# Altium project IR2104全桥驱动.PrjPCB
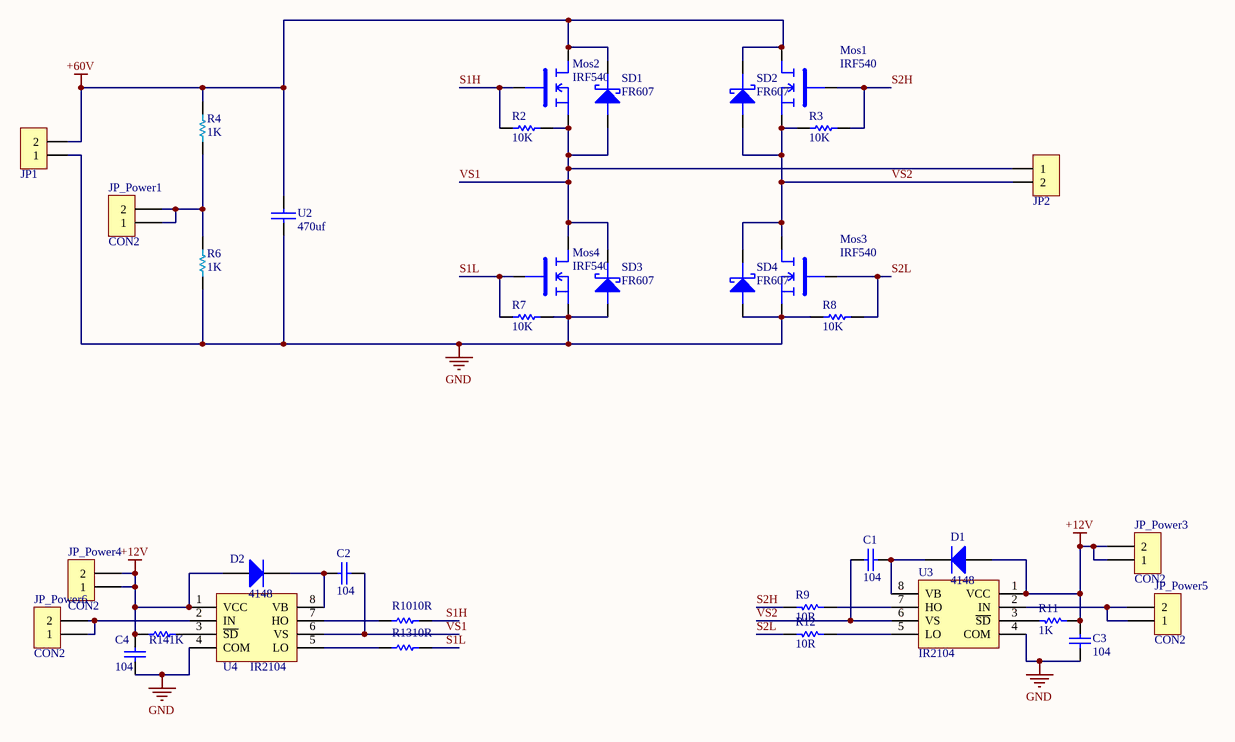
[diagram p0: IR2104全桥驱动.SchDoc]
1 sheet, 36 parts. Net scope: global (net labels, ports and power ports of the same name join across sheets).
Board file: PCB2.PcbDoc

## Sheet IR2104全桥驱动.SchDoc
size A4

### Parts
C1  value 104  [C 0805]  (hidden comment: Cap)
C2  value 104  [C 0805]  (hidden comment: Cap)
C3  value 104  [C 0805]  (hidden comment: Cap)
C4  value 104  [C 0805]  (hidden comment: Cap)
D1  4148  [D1206]
D2  4148  [D1206]
JP1  HDR-1X2  [KF301-2P]  (value not drawn)
JP2  HDR-1X2  [KF301-2P]  (value not drawn)
JP_Power1  CON2  [HDR-1x2]
JP_Power3  CON2  [HDR-1x2]
JP_Power4  CON2  [HDR-1x2]
JP_Power5  CON2  [HDR-1x2]
JP_Power6  CON2  [HDR-1x2]
Mos1  IRF540  [TO220A]
Mos2  IRF540  [TO220A]
Mos3  IRF540  [TO220A]
Mos4  IRF540  [TO220A]
R2  value 10K  [R 0805]  (hidden comment: Res1)
R3  value 10K  [R 0805]  (hidden comment: Res1)
R4  Values: 1K  [R 0805]  (hidden comment: RES)
R6  Values: 1K  [R 0805]  (hidden comment: RES)
R7  value 10K  [R 0805]  (hidden comment: Res1)
R8  value 10K  [R 0805]  (hidden comment: Res1)
R9  value 10R  [R 0805]  (hidden comment: Res1)
R10  value 10R  [R 0805]  (hidden comment: Res1)
R11  value 1K  [R 0805]  (hidden comment: Res1)
R12  value 10R  [R 0805]  (hidden comment: Res1)
R13  value 10R  [R 0805]  (hidden comment: Res1)
R14  value 1K  [R 0805]  (hidden comment: Res1)
SD1  FR607  [R-6]
SD2  FR607  [R-6]
SD3  FR607  [R-6]
SD4  FR607  [R-6]
U2  470uf  [CAP 10*22*31.5 - BK]
U3  IR2104  [SOP8_M]
U4  IR2104  [SOP8_M]

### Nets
+12V: C3.1 C4.1 D1.1(A) D2.1(A) JP_Power3.1 JP_Power3.2 JP_Power4.1 JP_Power4.2 R11.2 R14.2 U3.1(VCC) U4.1(VCC)
+60V: JP1.2 Mos1.2(D) Mos2.2(D) R4.2 SD1.2(K) SD2.2(K) U2.1
GND: C3.2 C4.2 JP1.1 Mos3.3(S) Mos4.3(S) R6.1 R7.1 R8.2 SD3.1(A) SD4.1(A) U2.2 U3.4(COM) U4.4(COM)
S1H: Mos2.1(G) R2.2 R10.2
S1L: Mos4.1(G) R7.2 R13.2
S2H: Mos1.1(G) R3.2 R9.2
S2L: Mos3.1(G) R8.1 R12.2
VS1: C2.1 JP2.1 Mos2.3(S) Mos4.2(D) R2.1 SD1.1(A) SD3.2(K) U4.6(VS)
VS2: C1.1 JP2.2 Mos1.3(S) Mos3.2(D) R3.1 SD2.1(A) SD4.2(K) U3.6(VS)
NetC1_2: C1.2 D1.2(K) U3.8(VB)
NetC2_2: C2.2 D2.2(K) U4.8(VB)
NetJP_Power1_1: JP_Power1.1 JP_Power1.2 R4.1 R6.2
NetJP_Power5_1: JP_Power5.1 JP_Power5.2 U3.2(IN)
NetJP_Power6_1: JP_Power6.1 JP_Power6.2 U4.2(IN)
NetR9_1: R9.1 U3.7(HO)
NetR10_1: R10.1 U4.7(HO)
NetR11_1: R11.1 U3.3(~{SD})
NetR12_1: R12.1 U3.5(LO)
NetR13_1: R13.1 U4.5(LO)
NetR14_1: R14.1 U4.3(~{SD})

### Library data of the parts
C1-C4 = Cap: Capacitor
D1 D2 = Diode: Default Diode
JP1 JP2 = Header 2: 2P接插件; 版权归属: 源创客
JP_Power1 JP_Power3-JP_Power6 = CON2: Connector
Mos1-Mos4 = NMOS
R2 R3 R7-R14 = Res1: Resistor
SD1-SD4 = 1N5822
U2 = CAP: Capacitor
